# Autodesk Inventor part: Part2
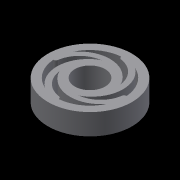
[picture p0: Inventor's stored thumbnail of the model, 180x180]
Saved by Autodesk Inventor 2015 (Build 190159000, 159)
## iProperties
Created: 2015-09
Part Number: Part2
Material: Generic
Document SubType Name: Modeling
Designer: Drano
Density: 1 g/cm^3
Appearance: Default
Author: Drano
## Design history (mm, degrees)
sketch "Sketch1"
  geometry: C1 r 15.95 at (0.312, 1.132); C2 r 5.75 at (0.312, 1.132); A1 r 12.95 centre (0.312, 1.132) between (-0.699, 14.042) and (-11.499, 6.441); A2 r 12.95 centre (0.312, 1.132) between (-12.598, 0.12) and (-4.997, -10.68); A3 r 12.95 centre (0.312, 1.132) between (1.324, -11.779) and (12.124, -4.178); A4 r 12.95 centre (0.312, 1.132) between (13.223, 2.143) and (5.622, 12.943); A5 r 8.75 centre (0.312, 1.132) between (8.284, 4.74) and (6.361, 7.454); A6 r 8.75 centre (0.312, 1.132) between (-3.296, 9.103) and (-6.01, 7.18); A7 r 8.75 centre (0.312, 1.132) between (-7.659, -2.476) and (-5.736, -5.191); A8 r 8.75 centre (0.312, 1.132) between (3.92, -6.84) and (6.635, -4.917); A9 r 11.603 centre (1.875, -1.331) between (-6.01, 7.18) and (-4.997, -10.68); A10 r 9.603 centre (1.875, -1.331) between (-7.659, -2.476) and (-0.059, -10.737); A11 r 5 centre (0.948, -5.84) between (-0.059, -10.737) and (0.419, -10.812); A12 r 1.012 centre (0.312, -11.818) between (1.324, -11.779) and (0.419, -10.812); A13 r 11.603 centre (2.775, 2.695) between (-5.736, -5.191) and (12.124, -4.178); A14 r 9.603 centre (2.775, 2.695) between (3.92, -6.84) and (12.181, 0.761); A15 r 5 centre (7.284, 1.768) between (12.181, 0.761) and (12.256, 1.239); A16 r 1.012 centre (13.262, 1.132) between (13.223, 2.143) and (12.256, 1.239); A17 r 11.603 centre (-1.251, 3.595) between (6.635, -4.917) and (5.622, 12.943); A18 r 9.603 centre (-1.251, 3.595) between (8.284, 4.74) and (0.683, 13.001); A19 r 5 centre (-0.324, 8.103) between (0.683, 13.001) and (0.205, 13.075); A20 r 1.012 centre (0.312, 14.082) between (-0.699, 14.042) and (0.205, 13.075); A21 r 11.603 centre (-2.151, -0.431) between (6.361, 7.454) and (-11.499, 6.441); A22 r 9.603 centre (-2.151, -0.431) between (-3.296, 9.103) and (-11.557, 1.503); A23 r 5 centre (-6.659, 0.496) between (-11.557, 1.503) and (-11.631, 1.025); A24 r 1.012 centre (-12.638, 1.132) between (-12.598, 0.12) and (-11.631, 1.025); 1 further point
  constraints: 48 point on circle, 26 centre point
extrude "Extrusion1" new body sketch "Sketch1" distance "d0" = 8; taper "d1" = 0 deg
body "Solid1"
